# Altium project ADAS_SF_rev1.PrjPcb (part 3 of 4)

## Sheet ADAS_SF_Data_Deserializer_Radar.SchDoc
size 431 x 279 mm; Date: Not shown in title block; ApprovedBy: Not shown in title block; CheckedBy: Not shown in title block; Author: Not shown in title block; CompanyName: Not shown in title block; Engineer: Not shown in title block; Organization: Not shown in title block; Address1: Not shown in title block; Address2: Not shown in title block; Address3: Not shown in title block; Address4: Not shown in title block; DocumentNumber: 1; Revision: Use project parameter SCH_Rev; SheetNumber: 8; SheetTotal: 15; PageSetup: Record=PageOptions¦CenterHorizontal=True¦CenterVertical=True¦PrintScale=0.66¦XCorrection=1.00¦YCorrection=1.00¦PrintKind=0¦BorderSize=5000000¦LeftOffset=0¦BottomOffset=0¦Orientation=2¦PaperLength=1000¦PaperWidth=1000¦Scale=100¦PaperSource=15¦PrintQuality=600¦MediaType=1¦DitherType=10¦PrintScaleMode=1¦PaperKind=Letter
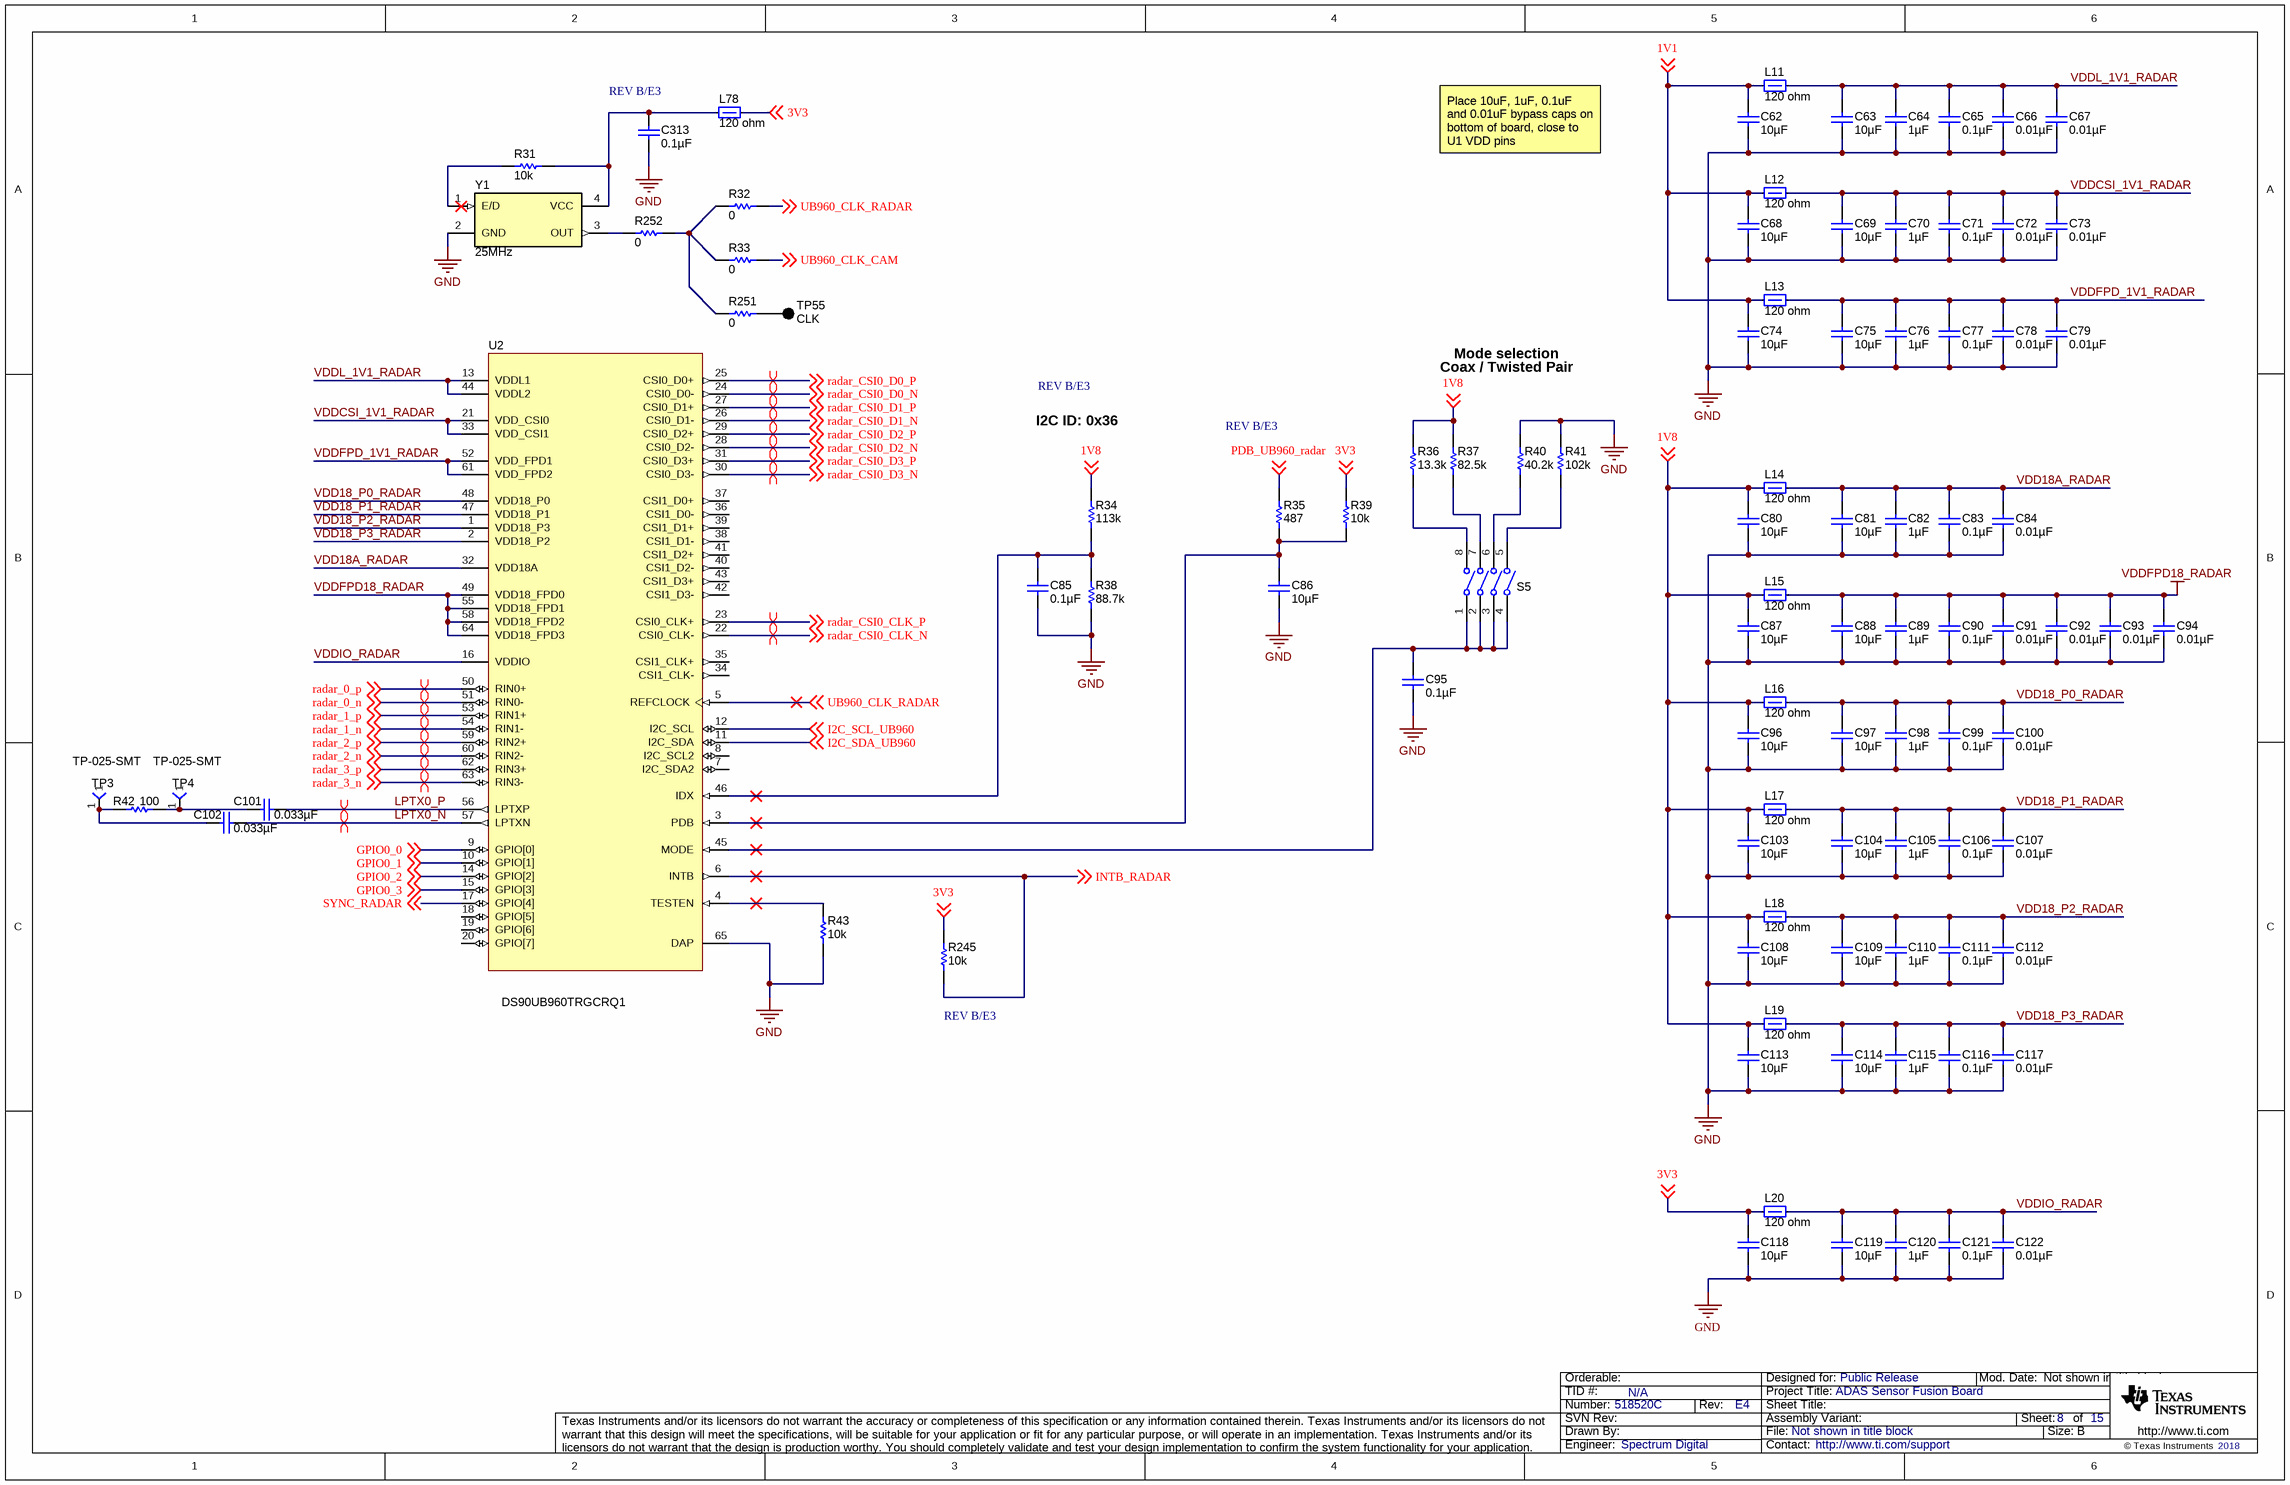
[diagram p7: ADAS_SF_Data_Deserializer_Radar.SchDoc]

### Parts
C62  ValueDisplayed: 10µF  [0805_HV]  (hidden comment: CL21A106KAFN3NE)
C63  ValueDisplayed: 10µF  [0805_HV]  (hidden comment: CL21A106KAFN3NE)
C64  ValueDisplayed: 1µF  [0402]  (hidden comment: C1005JB1V105K050BC)
C65  ValueDisplayed: 0.1µF  [0402]  (hidden comment: GCM155R71H104KE02D)
C66  ValueDisplayed: 0.01µF  [0402]  (hidden comment: GCM155R71H103KA55D)
C67  ValueDisplayed: 0.01µF  [0402]  (hidden comment: GCM155R71H103KA55D)
C68  ValueDisplayed: 10µF  [0805_HV]  (hidden comment: CL21A106KAFN3NE)
C69  ValueDisplayed: 10µF  [0805_HV]  (hidden comment: CL21A106KAFN3NE)
C70  ValueDisplayed: 1µF  [0402]  (hidden comment: C1005JB1V105K050BC)
C71  ValueDisplayed: 0.1µF  [0402]  (hidden comment: GCM155R71H104KE02D)
C72  ValueDisplayed: 0.01µF  [0402]  (hidden comment: GCM155R71H103KA55D)
C73  ValueDisplayed: 0.01µF  [0402]  (hidden comment: GCM155R71H103KA55D)
C74  ValueDisplayed: 10µF  [0805_HV]  (hidden comment: CL21A106KAFN3NE)
C75  ValueDisplayed: 10µF  [0805_HV]  (hidden comment: CL21A106KAFN3NE)
C76  ValueDisplayed: 1µF  [0402]  (hidden comment: C1005JB1V105K050BC)
C77  ValueDisplayed: 0.1µF  [0402]  (hidden comment: GCM155R71H104KE02D)
C78  ValueDisplayed: 0.01µF  [0402]  (hidden comment: GCM155R71H103KA55D)
C79  ValueDisplayed: 0.01µF  [0402]  (hidden comment: GCM155R71H103KA55D)
C80  ValueDisplayed: 10µF  [0805_HV]  (hidden comment: CL21A106KAFN3NE)
C81  ValueDisplayed: 10µF  [0805_HV]  (hidden comment: CL21A106KAFN3NE)
C82  ValueDisplayed: 1µF  [0402]  (hidden comment: C1005JB1V105K050BC)
C83  ValueDisplayed: 0.1µF  [0402]  (hidden comment: GCM155R71H104KE02D)
C84  ValueDisplayed: 0.01µF  [0402]  (hidden comment: GCM155R71H103KA55D)
C85  ValueDisplayed: 0.1µF  [0402]  (hidden comment: GCM155R71H104KE02D)
C86  ValueDisplayed: 10µF  [0805_HV]  (hidden comment: CL21A106KAFN3NE)
C87  ValueDisplayed: 10µF  [0805_HV]  (hidden comment: CL21A106KAFN3NE)
C88  ValueDisplayed: 10µF  [0805_HV]  (hidden comment: CL21A106KAFN3NE)
C89  ValueDisplayed: 1µF  [0402]  (hidden comment: C1005JB1V105K050BC)
C90  ValueDisplayed: 0.1µF  [0402]  (hidden comment: GCM155R71H104KE02D)
C91  ValueDisplayed: 0.01µF  [0402]  (hidden comment: GCM155R71H103KA55D)
C92  ValueDisplayed: 0.01µF  [0402]  (hidden comment: GCM155R71H103KA55D)
C93  ValueDisplayed: 0.01µF  [0402]  (hidden comment: GCM155R71H103KA55D)
C94  ValueDisplayed: 0.01µF  [0402]  (hidden comment: GCM155R71H103KA55D)
C95  ValueDisplayed: 0.1µF  [0402]  (hidden comment: GCM155R71H104KE02D)
C96  ValueDisplayed: 10µF  [0805_HV]  (hidden comment: CL21A106KAFN3NE)
C97  ValueDisplayed: 10µF  [0805_HV]  (hidden comment: CL21A106KAFN3NE)
C98  ValueDisplayed: 1µF  [0402]  (hidden comment: C1005JB1V105K050BC)
C99  ValueDisplayed: 0.1µF  [0402]  (hidden comment: GCM155R71H104KE02D)
C100  ValueDisplayed: 0.01µF  [0402]  (hidden comment: GCM155R71H103KA55D)
C101  ValueDisplayed: 0.033µF  [0402]  (hidden comment: CGA2B3X7R1H333K050BB)
C102  ValueDisplayed: 0.033µF  [0402]  (hidden comment: CGA2B3X7R1H333K050BB)
C103  ValueDisplayed: 10µF  [0805_HV]  (hidden comment: CL21A106KAFN3NE)
C104  ValueDisplayed: 10µF  [0805_HV]  (hidden comment: CL21A106KAFN3NE)
C105  ValueDisplayed: 1µF  [0402]  (hidden comment: C1005JB1V105K050BC)
C106  ValueDisplayed: 0.1µF  [0402]  (hidden comment: GCM155R71H104KE02D)
C107  ValueDisplayed: 0.01µF  [0402]  (hidden comment: GCM155R71H103KA55D)
C108  ValueDisplayed: 10µF  [0805_HV]  (hidden comment: CL21A106KAFN3NE)
C109  ValueDisplayed: 10µF  [0805_HV]  (hidden comment: CL21A106KAFN3NE)
C110  ValueDisplayed: 1µF  [0402]  (hidden comment: C1005JB1V105K050BC)
C111  ValueDisplayed: 0.1µF  [0402]  (hidden comment: GCM155R71H104KE02D)
C112  ValueDisplayed: 0.01µF  [0402]  (hidden comment: GCM155R71H103KA55D)
C113  ValueDisplayed: 10µF  [0805_HV]  (hidden comment: CL21A106KAFN3NE)
C114  ValueDisplayed: 10µF  [0805_HV]  (hidden comment: CL21A106KAFN3NE)
C115  ValueDisplayed: 1µF  [0402]  (hidden comment: C1005JB1V105K050BC)
C116  ValueDisplayed: 0.1µF  [0402]  (hidden comment: GCM155R71H104KE02D)
C117  ValueDisplayed: 0.01µF  [0402]  (hidden comment: GCM155R71H103KA55D)
C118  ValueDisplayed: 10µF  [0805_HV]  (hidden comment: CL21A106KAFN3NE)
C119  ValueDisplayed: 10µF  [0805_HV]  (hidden comment: CL21A106KAFN3NE)
C120  ValueDisplayed: 1µF  [0402]  (hidden comment: C1005JB1V105K050BC)
C121  ValueDisplayed: 0.1µF  [0402]  (hidden comment: GCM155R71H104KE02D)
C122  ValueDisplayed: 0.01µF  [0402]  (hidden comment: GCM155R71H103KA55D)
C313  ValueDisplayed: 0.1µF  [0402]  (hidden comment: GCM155R71H104KE02D)
L11  value 120 ohm  [0603]  (hidden comment: BLM18SG121TN1D)
L12  value 120 ohm  [0603]  (hidden comment: BLM18SG121TN1D)
L13  value 120 ohm  [0603]  (hidden comment: BLM18SG121TN1D)
L14  value 120 ohm  [0603]  (hidden comment: BLM18SG121TN1D)
L15  value 120 ohm  [0603]  (hidden comment: BLM18SG121TN1D)
L16  value 120 ohm  [0603]  (hidden comment: BLM18SG121TN1D)
L17  value 120 ohm  [0603]  (hidden comment: BLM18SG121TN1D)
L18  value 120 ohm  [0603]  (hidden comment: BLM18SG121TN1D)
L19  value 120 ohm  [0603]  (hidden comment: BLM18SG121TN1D)
L20  value 120 ohm  [0603]  (hidden comment: BLM18SG121TN1D)
L78  value 120 ohm  [0603]  (hidden comment: BLM18SG121TN1D)
R31  ValueDisplayed: 10k  [0402]  (hidden comment: CRCW040210K0JNED)
R32  ValueDisplayed: 0  [0603]  (hidden comment: CRCW06030000Z0EA)
R33  ValueDisplayed: 0  [0603]  (hidden comment: CRCW06030000Z0EA)
R34  ValueDisplayed: 113k  [0402]  (hidden comment: CRCW0402113KFKED)
R35  ValueDisplayed: 487  [0402]  (hidden comment: CRCW0402487RFKED)
R36  ValueDisplayed: 13.3k  [0402]  (hidden comment: CRCW040213K3FKED)
R37  ValueDisplayed: 82.5k  [0402]  (hidden comment: CRCW040282K5FKED)
R38  ValueDisplayed: 88.7k  [0402]  (hidden comment: CRCW040288K7FKED)
R39  ValueDisplayed: 10k  [0402]  (hidden comment: CRCW040210K0JNED)
R40  ValueDisplayed: 40.2k  [0402]  (hidden comment: CRCW040240K2FKED)
R41  ValueDisplayed: 102k  [0402]  (hidden comment: CRCW0402102KFKED)
R42  ValueDisplayed: 100  [0402]  (hidden comment: CRCW0402100RFKED)
R43  ValueDisplayed: 10k  [0402]  (hidden comment: CRCW040210K0JNED)
R245  ValueDisplayed: 10k  [0402]  (hidden comment: CRCW040210K0JNED)
R251  ValueDisplayed: 0  [0603]  (hidden comment: CRCW06030000Z0EA)
R252  ValueDisplayed: 0  [0603]  (hidden comment: CRCW06030000Z0EA)
S5  218-4LPST  [SW_218-4LPST]  (value not drawn)
TP3  TP-025-SMT  [TP_25MIL-SMT]
TP4  TP-025-SMT  [TP_25MIL-SMT]
TP55  CLK  [Keystone5011]
U2  DS90UB960TRGCRQ1  [RGC0064G]
Y1  Frequency: 25MHz  [TXC_7C]  (hidden comment: 7C-25.000MCB-T)

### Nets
1V1: C62.1 C68.1 C74.1 L11.1 L12.1 L13.1 ; off-sheet 1V1
1V8: C80.1 C87.1 C96.1 C103.1 C108.1 C113.1 L14.1 L15.1 L16.1 L17.1 L18.1 L19.1 R34.2 R36.2 R37.2 ; off-sheet 1V8
3V3: C118.1 L20.1 L78.2 R39.2 R245.2 ; off-sheet 3V3
GND: C62.2 C63.2 C64.2 C65.2 C66.2 C67.2 C68.2 C69.2 C70.2 C71.2 C72.2 C73.2 C74.2 C75.2 C76.2 C77.2 C78.2 C79.2 C80.2 C81.2 C82.2 C83.2 C84.2 C85.2 C86.2 C87.2 C88.2 C89.2 C90.2 C91.2 C92.2 C93.2 C94.2 C95.2 C96.2 C97.2 C98.2 C99.2 C100.2 C103.2 C104.2 C105.2 C106.2 C107.2 C108.2 C109.2 C110.2 C111.2 C112.2 C113.2 C114.2 C115.2 C116.2 C117.2 C118.2 C119.2 C120.2 C121.2 C122.2 C313.2 R38.1 R40.2 R41.2 R43.1 U2.65(DAP) Y1.2(GND)
VDDFPD18_RADAR: C88.1 C89.1 C90.1 C91.1 C92.1 C93.1 C94.1 L15.2 U2.49(VDD18_FPD0) U2.55(VDD18_FPD1) U2.58(VDD18_FPD2) U2.64(VDD18_FPD3)
GPIO0_0: U2.9(GPIO[0]) ; off-sheet GPIO0_0
GPIO0_1: U2.10(GPIO[1]) ; off-sheet GPIO0_1
GPIO0_2: U2.14(GPIO[2]) ; off-sheet GPIO0_2
GPIO0_3: U2.15(GPIO[3]) ; off-sheet GPIO0_3
I2C_SCL_UB960: U2.12(I2C_SCL) ; off-sheet I2C_SCL_UB960
I2C_SDA_UB960: U2.11(I2C_SDA) ; off-sheet I2C_SDA_UB960
INTB_RADAR: R245.1 U2.6(INTB) ; off-sheet INTB_RADAR
LPTX0_N: C102.1 U2.57(LPTXN)
LPTX0_P: C101.1 U2.56(LPTXP)
PDB_UB960_radar: R35.2 ; off-sheet PDB_UB960_radar
radar_0_n: U2.51(RIN0-) ; off-sheet radar_0_n
radar_0_p: U2.50(RIN0+) ; off-sheet radar_0_p
radar_1_n: U2.54(RIN1-) ; off-sheet radar_1_n
radar_1_p: U2.53(RIN1+) ; off-sheet radar_1_p
radar_2_n: U2.60(RIN2-) ; off-sheet radar_2_n
radar_2_p: U2.59(RIN2+) ; off-sheet radar_2_p
radar_3_n: U2.63(RIN3-) ; off-sheet radar_3_n
radar_3_p: U2.62(RIN3+) ; off-sheet radar_3_p
radar_CSI0_CLK_N: U2.22(CSI0_CLK-) ; off-sheet radar_CSI0_CLK_N
radar_CSI0_CLK_P: U2.23(CSI0_CLK+) ; off-sheet radar_CSI0_CLK_P
radar_CSI0_D0_N: U2.24(CSI0_D0-) ; off-sheet radar_CSI0_D0_N
radar_CSI0_D0_P: U2.25(CSI0_D0+) ; off-sheet radar_CSI0_D0_P
radar_CSI0_D1_N: U2.26(CSI0_D1-) ; off-sheet radar_CSI0_D1_N
radar_CSI0_D1_P: U2.27(CSI0_D1+) ; off-sheet radar_CSI0_D1_P
radar_CSI0_D2_N: U2.28(CSI0_D2-) ; off-sheet radar_CSI0_D2_N
radar_CSI0_D2_P: U2.29(CSI0_D2+) ; off-sheet radar_CSI0_D2_P
radar_CSI0_D3_N: U2.30(CSI0_D3-) ; off-sheet radar_CSI0_D3_N
radar_CSI0_D3_P: U2.31(CSI0_D3+) ; off-sheet radar_CSI0_D3_P
SYNC_RADAR: U2.17(GPIO[4]) ; off-sheet SYNC_RADAR
UB960_CLK_CAM: R33.2 ; off-sheet UB960_CLK_CAM
UB960_CLK_RADAR: R32.2 U2.5(REFCLOCK) ; off-sheet UB960_CLK_RADAR
VDD18_P0_RADAR: C97.1 C98.1 C99.1 C100.1 L16.2 U2.48(VDD18_P0)
VDD18_P1_RADAR: C104.1 C105.1 C106.1 C107.1 L17.2 U2.47(VDD18_P1)
VDD18_P2_RADAR: C109.1 C110.1 C111.1 C112.1 L18.2 U2.1(VDD18_P3)
VDD18_P3_RADAR: C114.1 C115.1 C116.1 C117.1 L19.2 U2.2(VDD18_P2)
VDD18A_RADAR: C81.1 C82.1 C83.1 C84.1 L14.2 U2.32(VDD18A)
VDDCSI_1V1_RADAR: C69.1 C70.1 C71.1 C72.1 C73.1 L12.2 U2.21(VDD_CSI0) U2.33(VDD_CSI1)
VDDFPD_1V1_RADAR: C75.1 C76.1 C77.1 C78.1 C79.1 L13.2 U2.52(VDD_FPD1) U2.61(VDD_FPD2)
VDDIO_RADAR: C119.1 C120.1 C121.1 C122.1 L20.2 U2.16(VDDIO)
VDDL_1V1_RADAR: C63.1 C64.1 C65.1 C66.1 C67.1 L11.2 U2.13(VDDL1) U2.44(VDDL2)
NetC85_1: C85.1 R34.1 R38.2 U2.46(IDX)
NetC86_1: C86.1 R35.1 R39.1 U2.3(PDB)
NetC95_1: C95.1 S5.1(A1) S5.2(A2) S5.3(A3) S5.4(A4) U2.45(MODE)
NetC101_2: C101.2 R42.1 TP4.1
NetC102_2: C102.2 R42.2 TP3.1
NetC313_1: C313.1 L78.1 R31.2 Y1.4(VCC)
NetR31_1: R31.1 Y1.1(E/D)
NetR32_1: R32.1 R33.1 R251.1 R252.2
NetR36_1: R36.1 S5.8(B1)
NetR37_1: R37.1 S5.7(B2)
NetR40_1: R40.1 S5.6(B3)
NetR41_1: R41.1 S5.5(B4)
NetR43_2: R43.2 U2.4(TESTEN)
NetR251_2: R251.2 TP55.1
NetR252_1: R252.1 Y1.3(OUT)

Not connected (* = marked no-connect by the designer): U2 7(I2C_SDA2) 8(I2C_SCL2) 18(GPIO[5]) 19(GPIO[6]) 20(GPIO[7]) 34(CSI1_CLK-) 35(CSI1_CLK+) 36(CSI1_D0-) 37(CSI1_D0+) 38(CSI1_D1-) 39(CSI1_D1+) 40(CSI1_D2-) 41(CSI1_D2+) 42(CSI1_D3-) 43(CSI1_D3+)

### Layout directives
differential pair: LPTX0_N, LPTX0_P, radar_0_n, radar_0_p, radar_1_n, radar_1_p, radar_2_n, radar_2_p, radar_3_n, radar_3_p, radar_CSI0_CLK_N, radar_CSI0_CLK_P, radar_CSI0_D0_N, radar_CSI0_D0_P, radar_CSI0_D1_N, radar_CSI0_D1_P, radar_CSI0_D2_N, radar_CSI0_D2_P, radar_CSI0_D3_N, radar_CSI0_D3_P

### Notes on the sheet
- (near C313) REV B/E3
- Place 10uF, 1uF, 0.1uF and 0.01uF bypass caps on bottom of board, close to U1 VDD pins
- Coax / Twisted Pair
- Mode selection
- REV B/E3
- I2C ID: 0x36
- (near R245) REV B/E3

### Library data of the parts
C62 C63 C68 C69 C74 C75 C80 C81 C87 C88 C96 C97 C103 C104 C108 C109 C113 C114 C118 C119 = CL21A106KAFN3NE: CAP, CERM, 10 µF, 25 V, +/- 10%, X5R, 0805; Manufacturer: Samsung; Polarized: N; CompType: Capacitor; Value: 10uF; U/M: EA; Cap_F: 0.00001; Tolerance_%: 10; Value1: Unknown; VDC_V: 25; Value2: 25V; TaMin_C: -55; TaMax_C: 85; Cap_Case: 0805
C64 C70 C76 C82 C89 C98 C105 C110 C115 C120 = C1005JB1V105K050BC: CAP, CERM, 1 µF, 35 V, +/- 10%, JB, 0402; Manufacturer: TDK; Polarized: N; CompType: Capacitor; Value: 1uF; U/M: EA; Cap_F: 0.000001; Tolerance_%: 10; Value1: Unknown; VDC_V: 35; Value2: 35V; TaMin_C: -25; TaMax_C: 85
C65 C71 C77 C83 C85 C90 C95 C99 C106 C111 C116 C121 C313 = GCM155R71H104KE02D: CAP, CERM, 0.1 µF, 50 V, +/- 10%, X7R, AEC-Q200 Grade 1, 0402; Manufacturer: MuRata; Polarized: N; CompType: Capacitor; Value: 0.1uF; U/M: EA; Cap_F: 0.0000001; Tolerance_%: 10; Value1: Unknown; VDC_V: 50; Value2: 50V; TaMin_C: -55; TaMax_C: 125; SizeArea_mm2: 0.5; SizeAreaWB_mm2: 3; SizeX_mm: 1; SizeZ_mm: 0.6; AEC Category: Q200; AEC Qualified: Y
C66 C67 C72 C73 C78 C79 C84 C91-C94 C100 C107 C112 C117 C122 = GCM155R71H103KA55D: CAP, CERM, 0.01uF, 50V, +/-10%, C0G/NP0, 0402; Manufacturer: MuRata; Polarized: N; CompType: Capacitor; U/M: EA; Cap_F: 0.00000001; Tolerance_%: 10; Value1: Unknown; VDC_V: 50; TaMin_C: -55; TaMax_C: 125
C86 = CL21A106KAFN3NE: CAP, CERM, 10 µF, 25 V, +/- 10%, X5R, 0805; Manufacturer: Samsung Electro-Mechanics; Polarized: N; CompType: Capacitor; Value: 10uF; U/M: EA; Cap_F: 0.00001; Tolerance_%: 10; Value1: Unknown; VDC_V: 25; Value2: 25V; TaMin_C: -55; TaMax_C: 85; Cap_Case: 0805; SizeArea_mm2: 2.5; SizeAreaWB_mm2: 6.75; SizeX_mm: 2; SizeY_mm: 1.25; SizeZ_mm: 1.45; AEC Category: Q200
C101 C102 = CGA2B3X7R1H333K050BB: CAP, CERM, 0.033 µF, 50 V, +/- 10%, X7R, AEC-Q200 Grade 1, 0402; Manufacturer: TDK; Polarized: N; CompType: Capacitor; Value: 0.033uF; U/M: EA; Cap_F: 0.000000033; Tolerance_%: 10; Value1: Unknown; VDC_V: 50; Value2: 50V; TaMin_C: -55; TaMax_C: 125; AEC Category: Q200; AEC Qualified: Y; AEC Grade: 1
L11-L13 L15-L19 L78 = BLM18SG331TN1D: 1.5A Ferrite Bead, 330 ohm @ 100MHz, SMD; Manufacturer: MuRata; Imax_A: 3; DCR_ohm: 25milliiohm; Value1: 25 milliohm; Value2: 3A; ZTyp@100MHz_Ohm: 120; U/M: EA
L14 L20 = BLM18SG121TN1D: Ferrite Bead, 120 ohm @ 100 MHz, 3 A, 0603; Manufacturer: MuRata; Imax_A: 3; DCR_ohm: 0.025; Value1: 0.025 ohm; Value2: 3A; ZTyp@100MHz_Ohm: 120
R31 R43 = CRCW040210K0JNED: RES, 10 k, 5%, 0.063 W, 0402; Manufacturer: Vishay-Dale; CompType: Resistor; Value: 10k; Res_ohm: 10000; Value_Code: 10k0; Tolerance_%: 5; Power_W: 0.063; Value2: 0.063W; VDC_V: 50; TempCo: 200 ppm/C; EIA_Code: E24; U/M: EA; AEC Category: Q200
R32 R33 R251 R252 = CRCW06030000Z0EA: RES, 0, 5%, 0.1 W, 0603; Manufacturer: Vishay-Dale; CompType: Resistor; Value: 0; Value_Code: 0000; Tolerance_%: 5; Power_W: 0.1; Value2: 0.1W; VDC_V: 75; TempCo: 200 ppm/C; SizeArea_mm2: 1.28; SizeX_mm: 1.6; SizeY_mm: 0.8; SizeZ_mm: 1; EIA_Code: E24; U/M: EA; AEC Category: Q200
R34 = CRCW0402113KFKED: RES, 113 k, 1%, 0.063 W, 0402; Manufacturer: Vishay-Dale; CompType: Resistor; Value: 113k; Res_ohm: 113000; Tolerance_%: 1; Power_W: 0.063; Value2: 0.063W; VDC_V: 50; TempCo: 100 ppm/C; EIA_Code: E96; U/M: EA; AEC Category: Q200; SizeArea_mm2: 0.5; SizeZ_mm: 0.6
R35 = CRCW0402487RFKED: RES, 487, 1%, 0.063 W, 0402; Manufacturer: Vishay-Dale; CompType: Resistor; Value: 487; Value_Code: 487R; Tolerance_%: 1; Power_W: 0.063; Value2: 0.063W; VDC_V: 50; TempCo: 100 ppm/C; EIA_Code: E96; U/M: EA; AEC Category: Q200; SizeArea_mm2: 0.5; SizeZ_mm: 0.6
R36 = CRCW040213K3FKED: RES, 13.3 k, 1%, 0.063 W, 0402; Manufacturer: Vishay-Dale; CompType: Resistor; Value: 13.3k; Res_ohm: 13300; Value_Code: 13k3; Tolerance_%: 1; Power_W: 0.063; Value2: 0.063W; VDC_V: 50; TempCo: 100 ppm/C; EIA_Code: E96; U/M: EA; AEC Category: Q200
R37 = CRCW040282K5FKED: RES, 82.5 k, 1%, 0.063 W, 0402; Manufacturer: Vishay-Dale; CompType: Resistor; Value: 82.5k; Res_ohm: 82500; Value_Code: 82k5; Tolerance_%: 1; Power_W: 0.063; Value2: 0.063W; VDC_V: 50; TempCo: 100 ppm/C; EIA_Code: E96; U/M: EA; AEC Category: Q200
R38 = CRCW040288K7FKED: RES, 88.7 k, 1%, 0.063 W, 0402; Manufacturer: Vishay-Dale; CompType: Resistor; Value: 88.7k; Res_ohm: 88700; Value_Code: 88k7; Tolerance_%: 1; Power_W: 0.063; Value2: 0.063W; VDC_V: 50; TempCo: 100 ppm/C; EIA_Code: E96; U/M: EA; AEC Category: Q200; SizeArea_mm2: 0.5; SizeZ_mm: 0.6
R39 R245 = CRCW040210K0JNED: RES, 10 k, 5%, 0.063 W, 0402; Manufacturer: Vishay-Dale; CompType: Resistor; Value: 10k; Res_ohm: 10000; Value_Code: 10k0; Tolerance_%: 5; Power_W: 0.063; Value2: 0.063W; VDC_V: 50; TempCo: 200 ppm/C; EIA_Code: E24; U/M: EA; AEC Category: Q200; SizeArea_mm2: 0.5; SizeX_mm: 1; SizeZ_mm: 0.6
R40 = CRCW040240K2FKED: RES, 40.2 k, 1%, 0.063 W, 0402; Manufacturer: Vishay-Dale; CompType: Resistor; Value: 40.2k; Res_ohm: 40200; Value_Code: 40k2; Tolerance_%: 1; Power_W: 0.063; Value2: 0.063W; VDC_V: 50; TempCo: 100 ppm/C; EIA_Code: E96; U/M: EA; AEC Category: Q200
R41 = CRCW0402102KFKED: RES, 102 k, 1%, 0.063 W, 0402; Manufacturer: Vishay-Dale; CompType: Resistor; Value: 102k; Res_ohm: 102000; Tolerance_%: 1; Power_W: 0.063; Value2: 0.063W; VDC_V: 50; TempCo: 100 ppm/C; EIA_Code: E96; U/M: EA; AEC Category: Q200
R42 = CRCW0402100RFKED: RES, 100, 1%, 0.063 W, 0402; Manufacturer: Vishay-Dale; CompType: Resistor; Value: 100; Value_Code: 100R; Tolerance_%: 1; Power_W: 0.063; Value2: 0.063W; VDC_V: 50; TempCo: 100 ppm/C; EIA_Code: E96; U/M: EA; AEC Category: Q200
S5 = 218-4LPST: Switch, Slide, SPST 4 poles, SMT; Manufacturer: CTS Electrocomponents; SymbolCreator: a0412235; VDC_V: 24; SwitchFunction: Off-On; PositionCount: 4; CurrentRating_mA: 25
TP3 TP4 = TP-025-SMT: Test Point, O.025"; Manufacturer: STD; Value: STD
TP55 = 5011: Test Point, Multipurpose, Black, TH; Manufacturer: Keystone; CompType: Test Point Loop; U/M: EA
U2 = DS90UB960TRGCRQ1: FPD-Link III Camera Hub Deserializer, RGC0064G; Alternate PartNumber: DS90UB960TRGCTQ1; Manufacturer: Texas Instruments; SymbolCreator: Altium; CompType: IC; U/M: EA
Y1 = 7C-25.000MCB-T: XO, 25.000MHz, 2.5V, SMD; Manufacturer: TXC Corporation; SymbolCreator: a0411947; CompType: Oscillator; U/M: EA; TaMin_C: -40; TaMax_C: 85; Frequency Stability: ±50ppm

## Sheet ADAS_SF_Data_Radar_Mux.SchDoc
size 431 x 279 mm; Date: Not shown in title block; ApprovedBy: Not shown in title block; CheckedBy: Not shown in title block; Author: Not shown in title block; CompanyName: Not shown in title block; Engineer: Not shown in title block; Organization: Not shown in title block; Address1: Not shown in title block; Address2: Not shown in title block; Address3: Not shown in title block; Address4: Not shown in title block; DocumentNumber: 1; Revision: Use project parameter SCH_Rev; SheetNumber: 9; SheetTotal: 15; PageSetup: Record=PageOptions¦CenterHorizontal=True¦CenterVertical=True¦PrintScale=1.00¦XCorrection=1.00¦YCorrection=1.00¦PrintKind=0¦BorderSize=5000000¦LeftOffset=0¦BottomOffset=0¦Orientation=2¦PaperLength=1000¦PaperWidth=1000¦Scale=100¦PaperSource=15¦PrintQuality=600¦MediaType=1¦DitherType=10¦PaperKind=Letter¦PrintScaleMode=1
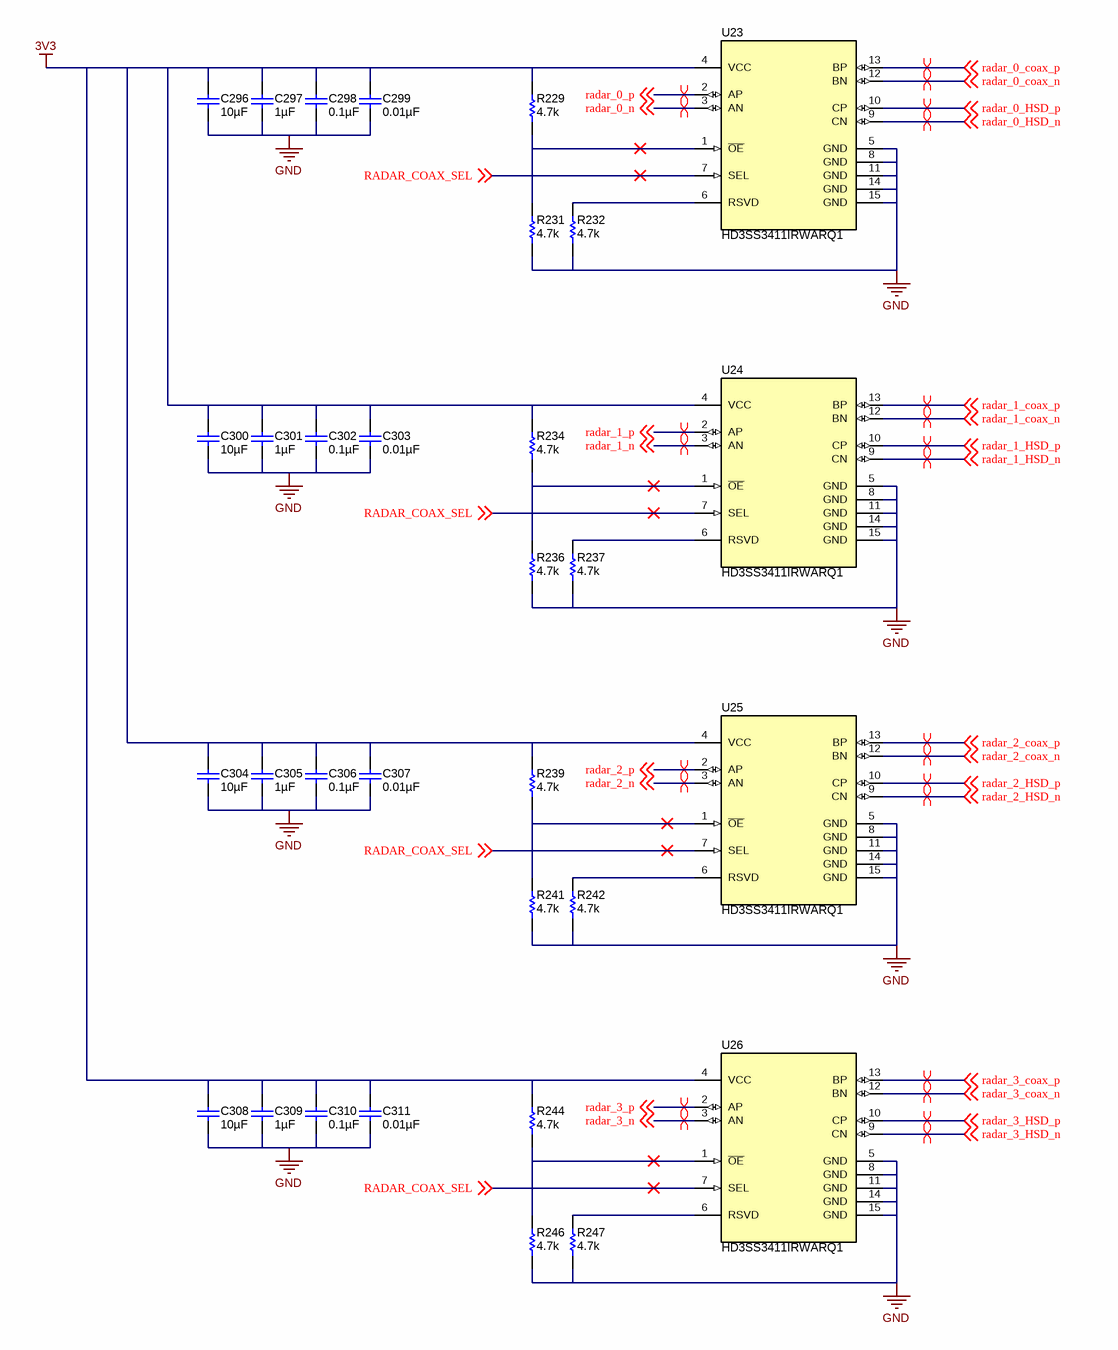
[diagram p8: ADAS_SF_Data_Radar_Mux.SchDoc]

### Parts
C296  ValueDisplayed: 10µF  [0805_HV]  (hidden comment: CL21A106KAFN3NE)
C297  ValueDisplayed: 1µF  [0402]  (hidden comment: C1005JB1V105K050BC)
C298  ValueDisplayed: 0.1µF  [0402]  (hidden comment: GCM155R71H104KE02D)
C299  ValueDisplayed: 0.01µF  [0402]  (hidden comment: GCM155R71H103KA55D)
C300  ValueDisplayed: 10µF  [0805_HV]  (hidden comment: CL21A106KAFN3NE)
C301  ValueDisplayed: 1µF  [0402]  (hidden comment: C1005JB1V105K050BC)
C302  ValueDisplayed: 0.1µF  [0402]  (hidden comment: GCM155R71H104KE02D)
C303  ValueDisplayed: 0.01µF  [0402]  (hidden comment: GCM155R71H103KA55D)
C304  ValueDisplayed: 10µF  [0805_HV]  (hidden comment: CL21A106KAFN3NE)
C305  ValueDisplayed: 1µF  [0402]  (hidden comment: C1005JB1V105K050BC)
C306  ValueDisplayed: 0.1µF  [0402]  (hidden comment: GCM155R71H104KE02D)
C307  ValueDisplayed: 0.01µF  [0402]  (hidden comment: GCM155R71H103KA55D)
C308  ValueDisplayed: 10µF  [0805_HV]  (hidden comment: CL21A106KAFN3NE)
C309  ValueDisplayed: 1µF  [0402]  (hidden comment: C1005JB1V105K050BC)
C310  ValueDisplayed: 0.1µF  [0402]  (hidden comment: GCM155R71H104KE02D)
C311  ValueDisplayed: 0.01µF  [0402]  (hidden comment: GCM155R71H103KA55D)
R229  ValueDisplayed: 4.7k  [0402]  (hidden comment: CRCW04024K70JNED)
R231  ValueDisplayed: 4.7k  [0402]  (hidden comment: CRCW04024K70JNED)
R232  ValueDisplayed: 4.7k  [0402]  (hidden comment: CRCW04024K70JNED)
R234  ValueDisplayed: 4.7k  [0402]  (hidden comment: CRCW04024K70JNED)
R236  ValueDisplayed: 4.7k  [0402]  (hidden comment: CRCW04024K70JNED)
R237  ValueDisplayed: 4.7k  [0402]  (hidden comment: CRCW04024K70JNED)
R239  ValueDisplayed: 4.7k  [0402]  (hidden comment: CRCW04024K70JNED)
R241  ValueDisplayed: 4.7k  [0402]  (hidden comment: CRCW04024K70JNED)
R242  ValueDisplayed: 4.7k  [0402]  (hidden comment: CRCW04024K70JNED)
R244  ValueDisplayed: 4.7k  [0402]  (hidden comment: CRCW04024K70JNED)
R246  ValueDisplayed: 4.7k  [0402]  (hidden comment: CRCW04024K70JNED)
R247  ValueDisplayed: 4.7k  [0402]  (hidden comment: CRCW04024K70JNED)
U23  HD3SS3411IRWARQ1  [RWA0014A]
U24  HD3SS3411IRWARQ1  [RWA0014A]
U25  HD3SS3411IRWARQ1  [RWA0014A]
U26  HD3SS3411IRWARQ1  [RWA0014A]

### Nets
3V3: C296.1 C297.1 C298.1 C299.1 C300.1 C301.1 C302.1 C303.1 C304.1 C305.1 C306.1 C307.1 C308.1 C309.1 C310.1 C311.1 R229.2 R234.2 R239.2 R244.2 U23.4(VCC) U24.4(VCC) U25.4(VCC) U26.4(VCC)
GND: C296.2 C297.2 C298.2 C299.2 C300.2 C301.2 C302.2 C303.2 C304.2 C305.2 C306.2 C307.2 C308.2 C309.2 C310.2 C311.2 R231.1 R232.1 R236.1 R237.1 R241.1 R242.1 R246.1 R247.1 U23.5(GND) U23.8(GND) U23.11(GND) U23.14(GND) U23.15(GND) U24.5(GND) U24.8(GND) U24.11(GND) U24.14(GND) U24.15(GND) U25.5(GND) U25.8(GND) U25.11(GND) U25.14(GND) U25.15(GND) U26.5(GND) U26.8(GND) U26.11(GND) U26.14(GND) U26.15(GND)
radar_0_coax_n: U23.12(BN) ; off-sheet radar_0_coax_n
radar_0_coax_p: U23.13(BP) ; off-sheet radar_0_coax_p
radar_0_HSD_n: U23.9(CN) ; off-sheet radar_0_HSD_n
radar_0_HSD_p: U23.10(CP) ; off-sheet radar_0_HSD_p
radar_0_n: U23.3(AN) ; off-sheet radar_0_n
radar_0_p: U23.2(AP) ; off-sheet radar_0_p
radar_1_coax_n: U24.12(BN) ; off-sheet radar_1_coax_n
radar_1_coax_p: U24.13(BP) ; off-sheet radar_1_coax_p
radar_1_HSD_n: U24.9(CN) ; off-sheet radar_1_HSD_n
radar_1_HSD_p: U24.10(CP) ; off-sheet radar_1_HSD_p
radar_1_n: U24.3(AN) ; off-sheet radar_1_n
radar_1_p: U24.2(AP) ; off-sheet radar_1_p
radar_2_coax_n: U25.12(BN) ; off-sheet radar_2_coax_n
radar_2_coax_p: U25.13(BP) ; off-sheet radar_2_coax_p
radar_2_HSD_n: U25.9(CN) ; off-sheet radar_2_HSD_n
radar_2_HSD_p: U25.10(CP) ; off-sheet radar_2_HSD_p
radar_2_n: U25.3(AN) ; off-sheet radar_2_n
radar_2_p: U25.2(AP) ; off-sheet radar_2_p
radar_3_coax_n: U26.12(BN) ; off-sheet radar_3_coax_n
radar_3_coax_p: U26.13(BP) ; off-sheet radar_3_coax_p
radar_3_HSD_n: U26.9(CN) ; off-sheet radar_3_HSD_n
radar_3_HSD_p: U26.10(CP) ; off-sheet radar_3_HSD_p
radar_3_n: U26.3(AN) ; off-sheet radar_3_n
radar_3_p: U26.2(AP) ; off-sheet radar_3_p
RADAR_COAX_SEL: U23.7(SEL) U24.7(SEL) U25.7(SEL) U26.7(SEL) ; off-sheet RADAR_COAX_SEL
NetR229_1: R229.1 R231.2 U23.1(~{OE})
NetR232_2: R232.2 U23.6(RSVD)
NetR234_1: R234.1 R236.2 U24.1(~{OE})
NetR237_2: R237.2 U24.6(RSVD)
NetR239_1: R239.1 R241.2 U25.1(~{OE})
NetR242_2: R242.2 U25.6(RSVD)
NetR244_1: R244.1 R246.2 U26.1(~{OE})
NetR247_2: R247.2 U26.6(RSVD)

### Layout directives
differential pair: radar_0_coax_n, radar_0_coax_p, radar_0_HSD_n, radar_0_HSD_p, radar_0_n, radar_0_p, radar_1_coax_n, radar_1_coax_p, radar_1_HSD_n, radar_1_HSD_p, radar_1_n, radar_1_p, radar_2_coax_n, radar_2_coax_p, radar_2_HSD_n, radar_2_HSD_p, radar_2_n, radar_2_p, radar_3_coax_n, radar_3_coax_p, radar_3_HSD_n, radar_3_HSD_p, radar_3_n, radar_3_p

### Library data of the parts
C296 C300 C304 C308 = CL21A106KAFN3NE: as C62 on sheet ADAS_SF_Data_Deserializer_Radar
C297 C301 C305 C309 = C1005JB1V105K050BC: as C64 on sheet ADAS_SF_Data_Deserializer_Radar
C298 C302 C306 C310 = GCM155R71H104KE02D: as C65 on sheet ADAS_SF_Data_Deserializer_Radar
C299 C303 C307 C311 = GCM155R71H103KA55D: as C66 on sheet ADAS_SF_Data_Deserializer_Radar
R229 R231 R232 R234 R236 R237 R239 R241 R242 R244 R246 R247 = CRCW04024K70JNED: RES, 4.7 k, 5%, 0.063 W, 0402; Manufacturer: Vishay-Dale; CompType: Resistor; Value: 4.7k; Res_ohm: 4700; Value_Code: 4k70; Tolerance_%: 5; Power_W: 0.063; Value2: 0.063W; VDC_V: 50; TempCo: 200 ppm/C; SizeArea_mm2: 0.5; SizeX_mm: 1; SizeZ_mm: 0.6; EIA_Code: E24; U/M: EA; AEC Category: Q200
U23-U26 = HD3SS3411IRWARQ1: One Channel Differential 2:1 Mux/Demux, RWA0014A; Alternate PartNumber: HD3SS3411IRWAQ1; Manufacturer: Texas Instruments; SymbolCreator: Altium; SizeArea_mm2: 12.25; SizeAreaWB_mm2: 20.25; SizeX_mm: 3.5; SizeZ_mm: 0.8; CompType: IC; U/M: EA

## Sheet ADAS_SF_Data_Connection_Radar_01.SchDoc
size 431 x 279 mm; Date: Not shown in title block; ApprovedBy: Not shown in title block; CheckedBy: Not shown in title block; Author: Not shown in title block; CompanyName: Not shown in title block; Engineer: Not shown in title block; Organization: Not shown in title block; Address1: Not shown in title block; Address2: Not shown in title block; Address3: Not shown in title block; Address4: Not shown in title block; DocumentNumber: 1; Revision: Use project parameter SCH_Rev; SheetNumber: 10; SheetTotal: 15; PageSetup: Record=PageOptions¦CenterHorizontal=True¦CenterVertical=True¦PrintScale=1.00¦XCorrection=1.00¦YCorrection=1.00¦PrintKind=0¦BorderSize=5000000¦LeftOffset=0¦BottomOffset=0¦Orientation=2¦PaperLength=1000¦PaperWidth=1000¦Scale=100¦PaperSource=15¦PrintQuality=600¦MediaType=1¦DitherType=10¦PaperKind=Letter¦PrintScaleMode=1
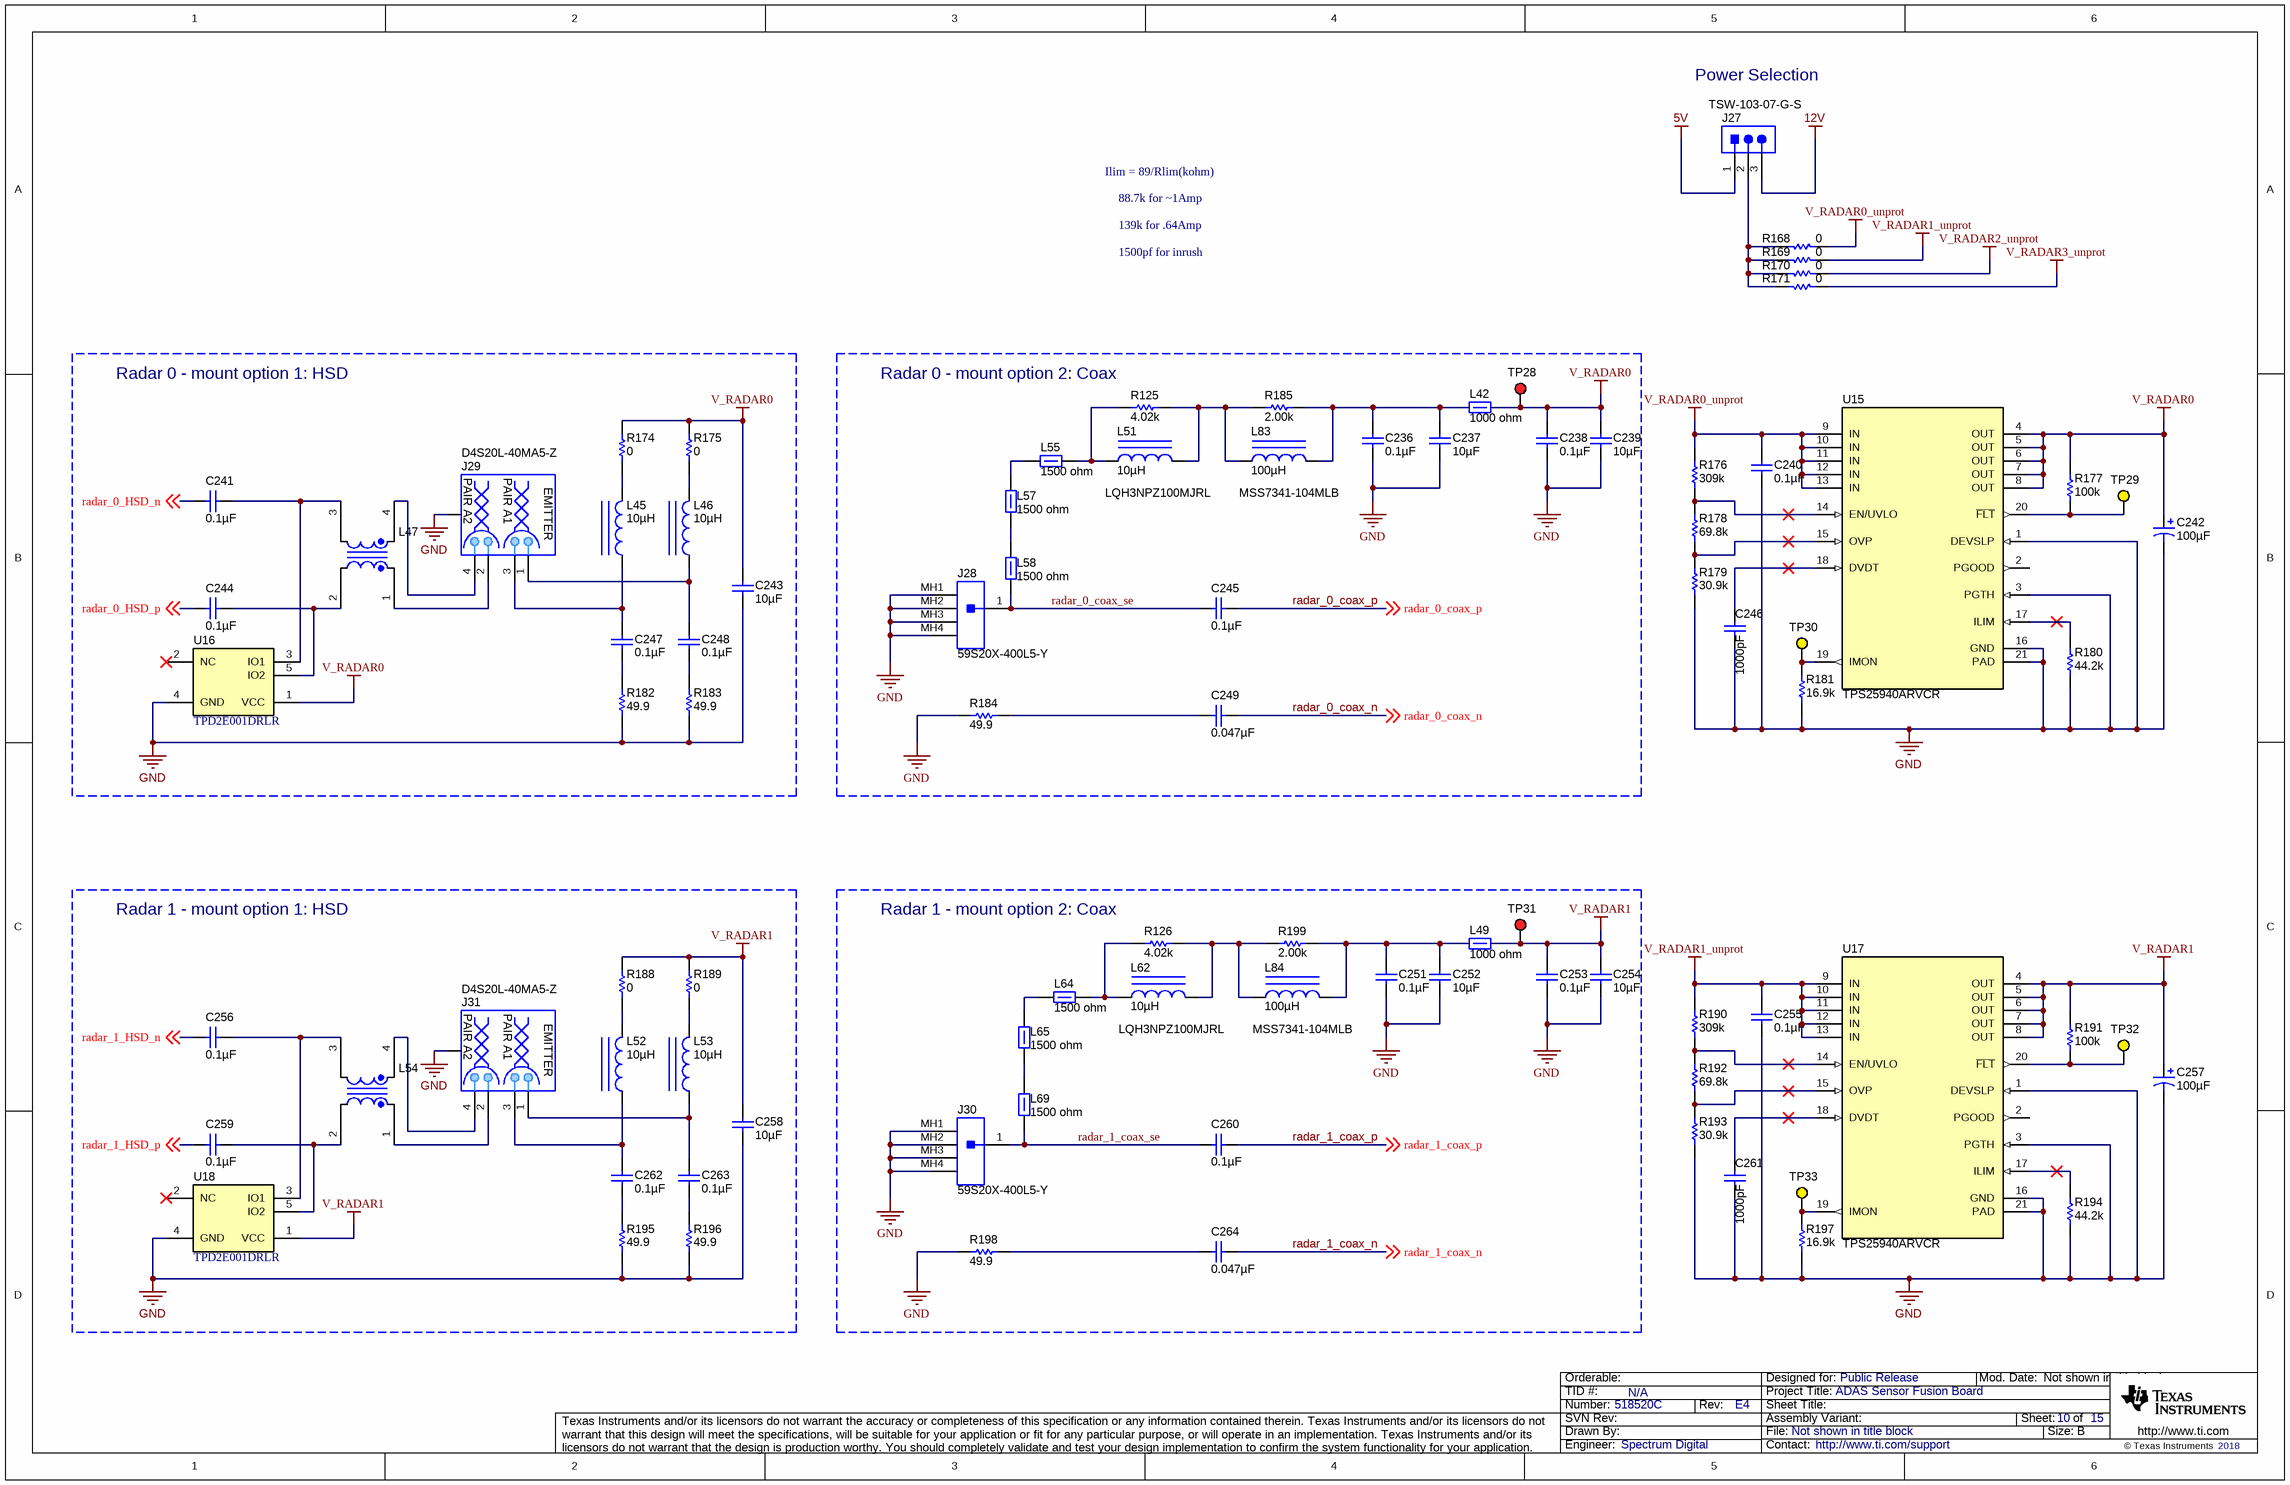
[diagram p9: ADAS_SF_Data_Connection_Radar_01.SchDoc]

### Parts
C236  ValueDisplayed: 0.1µF  [0402]  (hidden comment: GCM155R71H104KE02D)
C237  ValueDisplayed: 10µF  [0805_HV]  (hidden comment: TMK212BBJ106KG-T)
C238  ValueDisplayed: 0.1µF  [0402]  (hidden comment: GCM155R71H104KE02D)
C239  ValueDisplayed: 10µF  [0805_HV]  (hidden comment: TMK212BBJ106KG-T)
C240  ValueDisplayed: 0.1µF  [0603L]  (hidden comment: GRM188R72A104KA35D)
C241  ValueDisplayed: 0.1µF  [0402]  (hidden comment: GCM155R71H104KE02D)
C242  ValueDisplayed: 100µF  [SM_RADIAL_E]  (hidden comment: EEE-FC1C101P)
C243  ValueDisplayed: 10µF  [0805_HV]  (hidden comment: CL21A106KAFN3NE)
C244  ValueDisplayed: 0.1µF  [0402]  (hidden comment: GCM155R71H104KE02D)
C245  ValueDisplayed: 0.1µF  [0402]  (hidden comment: GCM155R71H104KE02D)
C246  ValueDisplayed: 1000pF  [0402]  (hidden comment: GCM155R71H102KA37D)
C247  ValueDisplayed: 0.1µF  [0603]  (hidden comment: GRM188R72A104KA35D)
C248  ValueDisplayed: 0.1µF  [0603]  (hidden comment: GRM188R72A104KA35D)
C249  ValueDisplayed: 0.047µF  [0402]  (hidden comment: CGA2B3X7R1H473K050BB)
C251  ValueDisplayed: 0.1µF  [0402]  (hidden comment: GCM155R71H104KE02D)
C252  ValueDisplayed: 10µF  [0805_HV]  (hidden comment: TMK212BBJ106KG-T)
C253  ValueDisplayed: 0.1µF  [0402]  (hidden comment: GCM155R71H104KE02D)
C254  ValueDisplayed: 10µF  [0805_HV]  (hidden comment: TMK212BBJ106KG-T)
C255  ValueDisplayed: 0.1µF  [0603L]  (hidden comment: GRM188R72A104KA35D)
C256  ValueDisplayed: 0.1µF  [0402]  (hidden comment: GCM155R71H104KE02D)
C257  ValueDisplayed: 100µF  [SM_RADIAL_E]  (hidden comment: EEE-FC1C101P)
C258  ValueDisplayed: 10µF  [0805_HV]  (hidden comment: CL21A106KAFN3NE)
C259  ValueDisplayed: 0.1µF  [0402]  (hidden comment: GCM155R71H104KE02D)
C260  ValueDisplayed: 0.1µF  [0402]  (hidden comment: GCM155R71H104KE02D)
C261  ValueDisplayed: 1000pF  [0402]  (hidden comment: GCM155R71H102KA37D)
C262  ValueDisplayed: 0.1µF  [0603]  (hidden comment: GRM188R72A104KA35D)
C263  ValueDisplayed: 0.1µF  [0603]  (hidden comment: GRM188R72A104KA35D)
C264  ValueDisplayed: 0.047µF  [0402]  (hidden comment: CGA2B3X7R1H473K050BB)
J27  TSW-103-07-G-S  [TSW-103-07-G-S]
J28  59S20X-400L5-Y  [Rosenberger_59S20X-400L5]
J29  D4S20L-40MA5-Z  [Rosenberger_D4S20L-40MA5]
J30  59S20X-400L5-Y  [Rosenberger_59S20X-400L5]
J31  D4S20L-40MA5-Z  [Rosenberger_D4S20L-40MA5]
L42  value 1000 ohm  [0603]  (hidden comment: MPZ1608S102ATA00)
L45  ValueDisplayed: 10µH  [EPL3012]  (hidden comment: EPL3012-103MLB)
L46  ValueDisplayed: 10µH  [EPL3012]  (hidden comment: EPL3012-103MLB)
L47  DLW21HN900SQ2L  [DLW21H]  (value not drawn)
L49  value 1000 ohm  [0603]  (hidden comment: MPZ1608S102ATA00)
L51  LQH3NPZ100MJRL  ValueDisplayed: 10µH  [LQH3NPZ_JR]
L52  ValueDisplayed: 10µH  [EPL3012]  (hidden comment: EPL3012-103MLB)
L53  ValueDisplayed: 10µH  [EPL3012]  (hidden comment: EPL3012-103MLB)
L54  DLW21HN900SQ2L  [DLW21H]  (value not drawn)
L55  ValueDisplayed: 1500 ohm  [0603]  (hidden comment: BLM18HE152SN1D)
L57  ValueDisplayed: 1500 ohm  [0603]  (hidden comment: BLM18HE152SN1D)
L58  ValueDisplayed: 1500 ohm  [0603]  (hidden comment: BLM18HE152SN1D)
L62  LQH3NPZ100MJRL  ValueDisplayed: 10µH  [LQH3NPZ_JR]
L64  ValueDisplayed: 1500 ohm  [0603]  (hidden comment: BLM18HE152SN1D)
L65  ValueDisplayed: 1500 ohm  [0603]  (hidden comment: BLM18HE152SN1D)
L69  ValueDisplayed: 1500 ohm  [0603]  (hidden comment: BLM18HE152SN1D)
L83  MSS7341-104MLB  ValueDisplayed: 100µH  [MSS7341]
L84  MSS7341-104MLB  ValueDisplayed: 100µH  [MSS7341]
R125  ValueDisplayed: 4.02k  [0603]  (hidden comment: CRCW06034K02FKEA)
R126  ValueDisplayed: 4.02k  [0603]  (hidden comment: CRCW06034K02FKEA)
R168  value 0  [0603]  (hidden comment: CRCW06030000Z0EA)
R169  value 0  [0603]  (hidden comment: CRCW06030000Z0EA)
R170  value 0  [0603]  (hidden comment: CRCW06030000Z0EA)
R171  value 0  [0603]  (hidden comment: CRCW06030000Z0EA)
R174  ValueDisplayed: 0  [0603]  (hidden comment: CRCW06030000Z0EA)
R175  ValueDisplayed: 0  [0603]  (hidden comment: CRCW06030000Z0EA)
R176  ValueDisplayed: 309k  [0402]  (hidden comment: CRCW0402309KFKED)
R177  ValueDisplayed: 100k  [0402]  (hidden comment: CRCW0402100KDHEDP)
R178  ValueDisplayed: 69.8k  [0402]  (hidden comment: CRCW040269K8FKED)
R179  ValueDisplayed: 30.9k  [0402]  (hidden comment: CRCW040230K9FKED)
R180  ValueDisplayed: 44.2k  [0402]  (hidden comment: CRCW040244K2FKED)
R181  ValueDisplayed: 16.9k  [0402]  (hidden comment: CRCW040216K9FKED)
R182  ValueDisplayed: 49.9  [0402]  (hidden comment: CRCW040249R9FKED)
R183  ValueDisplayed: 49.9  [0402]  (hidden comment: CRCW040249R9FKED)
R184  ValueDisplayed: 49.9  [0402]  (hidden comment: CRCW040249R9FKED)
R185  ValueDisplayed: 2.00k  [0603]  (hidden comment: CRCW06032K00FKEA)
R188  ValueDisplayed: 0  [0603]  (hidden comment: CRCW06030000Z0EA)
R189  ValueDisplayed: 0  [0603]  (hidden comment: CRCW06030000Z0EA)
R190  ValueDisplayed: 309k  [0402]  (hidden comment: CRCW0402309KFKED)
R191  ValueDisplayed: 100k  [0402]  (hidden comment: CRCW0402100KDHEDP)
R192  ValueDisplayed: 69.8k  [0402]  (hidden comment: CRCW040269K8FKED)
R193  ValueDisplayed: 30.9k  [0402]  (hidden comment: CRCW040230K9FKED)
R194  ValueDisplayed: 44.2k  [0402]  (hidden comment: CRCW040244K2FKED)
R195  ValueDisplayed: 49.9  [0402]  (hidden comment: CRCW040249R9FKED)
R196  ValueDisplayed: 49.9  [0402]  (hidden comment: CRCW040249R9FKED)
R197  ValueDisplayed: 16.9k  [0402]  (hidden comment: CRCW040216K9FKED)
R198  ValueDisplayed: 49.9  [0402]  (hidden comment: CRCW040249R9FKED)
R199  ValueDisplayed: 2.00k  [0603]  (hidden comment: CRCW06032K00FKEA)
TP28  5000  [Keystone5000]  (value not drawn)
TP29  5004  [Keystone5004]  (value not drawn)
TP30  5004  [Keystone5004]  (value not drawn)
TP31  5000  [Keystone5000]  (value not drawn)
TP32  5004  [Keystone5004]  (value not drawn)
TP33  5004  [Keystone5004]  (value not drawn)
U15  TPS25940ARVCR  [RVC0020A]
U16  TPD2E001DRLR  [DRL0005A]
U17  TPS25940ARVCR  [RVC0020A]
U18  TPD2E001DRLR  [DRL0005A]

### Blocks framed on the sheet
Radar 0 - mount option 1: HSD: C241 C243 C244 C247 C248 J29 L45-L47 R174 R175 R182 R183 U16
Radar 0 - mount option 2: Coax: C236-C239 C245 C249 J28 L42 L51 L55 L57 L58 L83 R125 R184 R185 TP28
Radar 1 - mount option 1: HSD: C256 C258 C259 C262 C263 J31 L52-L54 R188 R189 R195 R196 U18
Radar 1 - mount option 2: Coax: C251-C254 C260 C264 J30 L49 L62 L64 L65 L69 L84 R126 R198 R199 TP31

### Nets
5V: J27.1
12V: J27.3
GND: C236.2 C237.2 C238.2 C239.2 C240.1 C242.2(-) C243.2 C246.2 C251.2 C252.2 C253.2 C254.2 C255.1 C257.2(-) C258.2 C261.2 J28.MH1 J28.MH2 J28.MH3 J28.MH4 J29.MH J30.MH1 J30.MH2 J30.MH3 J30.MH4 J31.MH R179.1 R180.1 R181.1 R182.1 R183.1 R184.1 R193.1 R194.1 R195.1 R196.1 R197.1 R198.1 U15.1(DEVSLP) U15.3(PGTH) U15.16(GND) U15.21(PAD) U16.4(GND) U17.1(DEVSLP) U17.3(PGTH) U17.16(GND) U17.21(PAD) U18.4(GND)
V_RADAR0: C238.1 C239.1 C242.1(+) C243.1 L42.2 R174.2 R175.2 R177.2 TP28.1 U15.4(OUT) U15.5(OUT) U15.6(OUT) U15.7(OUT) U15.8(OUT) U16.1(VCC)
V_RADAR0_unprot: C240.2 R168.1 R176.2 U15.9(IN) U15.10(IN) U15.11(IN) U15.12(IN) U15.13(IN)
V_RADAR1: C253.1 C254.1 C257.1(+) C258.1 L49.2 R188.2 R189.2 R191.2 TP31.1 U17.4(OUT) U17.5(OUT) U17.6(OUT) U17.7(OUT) U17.8(OUT) U18.1(VCC)
V_RADAR1_unprot: C255.2 R169.1 R190.2 U17.9(IN) U17.10(IN) U17.11(IN) U17.12(IN) U17.13(IN)
V_RADAR2_unprot: R170.1
V_RADAR3_unprot: R171.1
radar_0_coax_n: C249.2 ; off-sheet radar_0_coax_n
radar_0_coax_p: C245.1 ; off-sheet radar_0_coax_p
radar_0_coax_se: C245.2 J28.1 L58.1
radar_0_HSD_n: C241.2 ; off-sheet radar_0_HSD_n
radar_0_HSD_p: C244.2 ; off-sheet radar_0_HSD_p
radar_1_coax_n: C264.2 ; off-sheet radar_1_coax_n
radar_1_coax_p: C260.1 ; off-sheet radar_1_coax_p
radar_1_coax_se: C260.2 J30.1 L69.1
radar_1_HSD_n: C256.2 ; off-sheet radar_1_HSD_n
radar_1_HSD_p: C259.2 ; off-sheet radar_1_HSD_p
NetC236_1: C236.1 C237.1 L42.1 L83.2 R185.2
NetC241_1: C241.1 L47.3 U16.3(IO1)
NetC244_1: C244.1 L47.2 U16.5(IO2)
NetC246_1: C246.1 U15.18(DVDT)
NetC247_1: C247.1 J29.3 L45.1
NetC247_2: C247.2 R182.2
NetC248_1: C248.1 J29.1 L46.1
NetC248_2: C248.2 R183.2
NetC249_1: C249.1 R184.2
NetC251_1: C251.1 C252.1 L49.1 L84.2 R199.2
NetC256_1: C256.1 L54.3 U18.3(IO1)
NetC259_1: C259.1 L54.2 U18.5(IO2)
NetC261_1: C261.1 U17.18(DVDT)
NetC262_1: C262.1 J31.3 L52.1
NetC262_2: C262.2 R195.2
NetC263_1: C263.1 J31.1 L53.1
NetC263_2: C263.2 R196.2
NetC264_1: C264.1 R198.2
NetJ27_2: J27.2 R168.2 R169.2 R170.2 R171.2
NetJ29_2: J29.2 L47.1
NetJ29_4: J29.4 L47.4
NetJ31_2: J31.2 L54.1
NetJ31_4: J31.4 L54.4
NetL45_2: L45.2 R174.1
NetL46_2: L46.2 R175.1
NetL51_1: L51.1 L55.2 R125.1
NetL51_2: L51.2 L83.1 R125.2 R185.1
NetL52_2: L52.2 R188.1
NetL53_2: L53.2 R189.1
NetL55_1: L55.1 L57.2
NetL57_1: L57.1 L58.2
NetL62_1: L62.1 L64.2 R126.1
NetL62_2: L62.2 L84.1 R126.2 R199.1
NetL64_1: L64.1 L65.2
NetL65_1: L65.1 L69.2
NetR176_1: R176.1 R178.2 U15.14(EN/UVLO)
NetR177_1: R177.1 TP29.1 U15.20(~{FLT})
NetR178_1: R178.1 R179.2 U15.15(OVP)
NetR180_2: R180.2 U15.17(ILIM)
NetR181_2: R181.2 TP30.1 U15.19(IMON)
NetR190_1: R190.1 R192.2 U17.14(EN/UVLO)
NetR191_1: R191.1 TP32.1 U17.20(~{FLT})
NetR192_1: R192.1 R193.2 U17.15(OVP)
NetR194_2: R194.2 U17.17(ILIM)
NetR197_2: R197.2 TP33.1 U17.19(IMON)

Not connected (* = marked no-connect by the designer): U15 2(PGOOD); U16 2(NC)*; U17 2(PGOOD); U18 2(NC)*

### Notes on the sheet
- Power Selection
- Ilim = 89/Rlim(kohm)
- 88.7k for
  Amp
- 139k for .64Amp
- 1500pf for inrush

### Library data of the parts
C236 C238 C241 C244 C245 C251 C253 C256 C259 C260 = GCM155R71H104KE02D: as C65 on sheet ADAS_SF_Data_Deserializer_Radar
C237 C239 C252 C254 = TMK212BBJ106KG-T: CAP, CERM, 10 µF, 25 V, +/- 10%, X5R, 0805; Manufacturer: Taiyo Yuden; Polarized: N; CompType: Capacitor; Value: 10uF; U/M: EA; Cap_F: 0.00001; Tolerance_%: 10; Value1: Unknown; VDC_V: 25; Value2: 25V; TaMin_C: -55; TaMax_C: 85; Cap_Case: 0805; SizeArea_mm2: 2.5; SizeAreaWB_mm2: 6.75; SizeX_mm: 2; SizeY_mm: 1.25; SizeZ_mm: 1.45; AEC Category: Q200
C240 C255 = GRM188R72A104KA35D: CAP, CERM, 0.1uF, 100V, +/-10%, X7R, 0603; Manufacturer: MuRata; Polarized: N; CompType: Capacitor; U/M: EA; Cap_F: 0.0000001; Tolerance_%: 10; Value1: Unknown; VDC_V: 100; TaMin_C: -55; TaMax_C: 125; Cap_Case: 0603
C242 C257 = EEE-FC1C101P: CAP, AL, 100 µF, 16 V, +/- 20%, 0.4 ohm, SMD; Manufacturer: Panasonic; Polarized: Y; CompType: Capacitor; Value: 100uF; U/M: EA; Cap_F: 0.0001; Tolerance_%: 20; Value1: 0.4 ohm; VDC_V: 16; Value2: 16V; ESR_ohm: 0.4; IRMS_A: 0.15; TaMin_C: -40; TaMax_C: 105; Cap_Case: E; AEC Category: Q200
C243 C258 = CL21A106KAFN3NE: as C62 on sheet ADAS_SF_Data_Deserializer_Radar
C246 C261 = GCM155R71H102KA37D: CAP, CERM, 1000 pF, 50 V, +/- 10%, X7R, AEC-Q200 Grade 1, 0402; Manufacturer: MuRata; Polarized: N; CompType: Capacitor; Value: 1000pF; U/M: EA; Cap_F: 0.000000001; Tolerance_%: 10; Value1: Unknown; VDC_V: 50; Value2: 50V; TaMin_C: -55; TaMax_C: 125; SizeArea_mm2: 0.5; SizeAreaWB_mm2: 3; SizeX_mm: 1; SizeZ_mm: 0.6; AEC Category: Q200; AEC Qualified: Y
C247 C248 C262 C263 = GRM188R72A104KA35D: CAP, CERM, 0.1 µF, 100 V, +/- 10%, X7R, 0603; Manufacturer: MuRata; Polarized: N; CompType: Capacitor; Value: 0.1uF; U/M: EA; Cap_F: 0.0000001; Tolerance_%: 10; Value1: Unknown; VDC_V: 100; Value2: 100V; TaMin_C: -55; TaMax_C: 125; SizeArea_mm2: 1.28; SizeAreaWB_mm2: 4.68; SizeX_mm: 1.6; SizeY_mm: 0.8; SizeZ_mm: 1; AEC Category: Q200
C249 C264 = CGA2B3X7R1H473K050BB: CAP, CERM, 0.047 µF, 50 V, +/- 10%, X7R, AEC-Q200 Grade 1, 0402; Manufacturer: TDK; Polarized: N; CompType: Capacitor; Value: 0.047uF; U/M: EA; Cap_F: 0.000000047; Tolerance_%: 10; ESR_ohm: 0.06407; Value1: 0.06407 ohm; VDC_V: 50; Value2: 50V; IRMS_A: 0.646122; TaMin_C: -55; TaMax_C: 125; SizeArea_mm2: 0.5; SizeAreaWB_mm2: 3; SizeX_mm: 1; SizeZ_mm: 0.6; AEC Category: Q200; AEC Qualified: Y
J27 = TSW-103-07-G-S: Header, 100mil, 3x1, Gold, TH; Manufacturer: Samtec; SymbolCreator: a0799628; Pitch_mm: 2.54; Gender: Male; Shrouded: N; Row_Count: 1; Current_A: 6.3; Voltage_V: 550; Cert_CSA: Y
J28 J30 = 59S20X-400L5-Y: RIGHT ANGLE PLUG FOR PCB; Manufacturer: Rosenberger; SymbolCreator: x0208325; U/M: EA
J29 J31 = D4S20L-40MA5-Z: Right Angle Plug for PCB, TH; Manufacturer: Rosenberger; SymbolCreator: Altium/a0412235
L42 L49 = MPZ1608S102ATA00: Ferrite Bead, 1000 ohm @ 100 MHz, 0.8 A, 0603; Manufacturer: TDK; Imax_A: 0.8; DCR_ohm: 0.3; Value1: 0.3 ohm; Value2: 0.8A; ZTyp@100MHz_Ohm: 1000
L45 L46 L52 L53 = EPL3012-103MLB: Inductor, Shielded, Ferrite, 10 µH, 0.79 A, 0.32 ohm, SMD; Manufacturer: Coilcraft; Value: 10uH; Ind_H: 10.0E-6; Imax_A: 0.79; Irms: 0.79A @ 40C rise; Isat: 0.8A @ 30% inductance drop; DCR_ohm: 0.32; Value2: 0.79A; AEC Category: Q200
L47 L54 = DLW21HN900SQ2L: Coupled inductor, 0.33 A, 0.35 ohm, SMD; Manufacturer: MuRata; SymbolCreator: a0412235; DCR_ohm: 0.35
L51 L62 = LQH3NPZ100MJRL: Inductor, Wirewound, Ferrite, 10 µH, 0.81 A, 0.288 ohm, AEC-Q200 Grade 1, SMD; Manufacturer: MuRata; Value: 10uH; Ind_H: 10.0E-6; Imax_A: 0.81; Irms: 1.2A @ 40C rise; Isat: 0.81A @ 30% inductance drop; DCR_ohm: 0.288; Value2: 0.81A; SizeAreaWB_mm2: 16; SizeArea_mm2: 9; SizeX_mm: 3; SizeZ_mm: 1.2; AEC Category: Q200; AEC Qualified: Y; AEC Grade: 1
L55 L57 L58 L64 L65 L69 = BLM18HE152SN1D: Ferrite Bead, 1500 ohm @ 100 MHz, 0.5 A, 0603; Manufacturer: MuRata; Imax_A: 0.5; Value1: 0.5 ohm; Value2: 0.5A; SizeAreaWB_mm2: 4.68; SizeArea_mm2: 1.28; SizeX_mm: 1.6; SizeY_mm: 0.8; SizeZ_mm: 1; ZTyp@100MHz_Ohm: 1500
L83 L84 = MSS7341-104MLB: Inductor, Shielded Drum Core, Ferrite, 100 µH, 0.71 A, 0.36 ohm, SMD; Manufacturer: Coilcraft; Value: 100uH; Ind_H: 100.0E-6; Imax_A: 0.71; Irms: 1.15A @ 40C rise; Isat: 0.71A @ 30% inductance drop; DCR_ohm: 0.36; Value2: 0.71A; SizeAreaWB_mm2: 86.49; SizeArea_mm2: 53.29; SizeX_mm: 7.3; SizeZ_mm: 4.1; AEC Category: Q200; AEC Qualified: N
R125 R126 = CRCW06034K02FKEA: RES, 4.02 k, 1%, 0.1 W, 0603; Manufacturer: Vishay-Dale; CompType: Resistor; Value: 4.02k; Res_ohm: 4020; Value_Code: 4k02; Tolerance_%: 1; Power_W: 0.1; Value2: 0.1W; VDC_V: 75; TempCo: 100 ppm/C; SizeArea_mm2: 1.28; SizeX_mm: 1.6; SizeY_mm: 0.8; EIA_Code: E96; U/M: EA; AEC Category: Q200
R168-R171 = CRCW06030000Z0EA: RES, 0 ohm, 5%, 0.1W, 0603; Manufacturer: Vishay-Dale; CompType: Resistor; Value_Code: 0000; Tolerance_%: 5; Power_W: 0.1; VDC_V: 75; TempCo: 200 ppm/C; EIA_Code: E24; U/M: EA
R174 R175 R188 R189 = CRCW06030000Z0EA: as R32 on sheet ADAS_SF_Data_Deserializer_Radar
R176 R190 = CRCW0402309KFKED: RES, 309 k, 1%, 0.063 W, 0402; Manufacturer: Vishay-Dale; CompType: Resistor; Value: 309k; Res_ohm: 309000; Tolerance_%: 1; Power_W: 0.063; Value2: 0.063W; VDC_V: 50; TempCo: 100 ppm/C; SizeArea_mm2: 0.5; SizeZ_mm: 0.6; EIA_Code: E96; U/M: EA; AEC Category: Q200
R177 R191 = CRCW0402100KDHEDP: RES, 100 k, 0.5%, 0.063 W, 0402; Manufacturer: Vishay-Dale; CompType: Resistor; Value: 100k; Res_ohm: 100000; Tolerance_%: 0.5; Power_W: 0.063; Value2: 0.063W; VDC_V: 50; TempCo: 50 ppm/C; SizeX_mm: 1; SizeZ_mm: 0.6; EIA_Code: E192; U/M: EA; AEC Category: Q200
R178 R192 = CRCW040269K8FKED: RES, 69.8 k, 1%, 0.063 W, 0402; Manufacturer: Vishay-Dale; CompType: Resistor; Value: 69.8k; Res_ohm: 69800; Value_Code: 69k8; Tolerance_%: 1; Power_W: 0.063; Value2: 0.063W; VDC_V: 50; TempCo: 100 ppm/C; SizeArea_mm2: 0.5; SizeZ_mm: 0.6; EIA_Code: E96; U/M: EA; AEC Category: Q200
R179 R193 = CRCW040230K9FKED: RES, 30.9 k, 1%, 0.063 W, 0402; Manufacturer: Vishay-Dale; CompType: Resistor; Value: 30.9k; Res_ohm: 30900; Value_Code: 30k9; Tolerance_%: 1; Power_W: 0.063; Value2: 0.063W; VDC_V: 50; TempCo: 100 ppm/C; SizeArea_mm2: 0.5; SizeZ_mm: 0.6; EIA_Code: E96; U/M: EA; AEC Category: Q200
R180 R194 = CRCW040244K2FKED: RES, 44.2 k, 1%, 0.063 W, 0402; Manufacturer: Vishay-Dale; CompType: Resistor; Value: 44.2k; Res_ohm: 44200; Value_Code: 44k2; Tolerance_%: 1; Power_W: 0.063; Value2: 0.063W; VDC_V: 50; TempCo: 100 ppm/C; SizeArea_mm2: 0.5; SizeZ_mm: 0.6; EIA_Code: E96; U/M: EA; AEC Category: Q200
R181 R197 = CRCW040216K9FKED: RES, 16.9 k, 1%, 0.063 W, 0402; Manufacturer: Vishay-Dale; CompType: Resistor; Value: 16.9k; Res_ohm: 16900; Value_Code: 16k9; Tolerance_%: 1; Power_W: 0.063; Value2: 0.063W; VDC_V: 50; TempCo: 100 ppm/C; SizeArea_mm2: 0.5; SizeZ_mm: 0.6; EIA_Code: E96; U/M: EA; AEC Category: Q200
R182 R183 R195 R196 = CRCW040249R9FKED: RES, 49.9, 1%, 0.063 W, 0402; Manufacturer: Vishay-Dale; CompType: Resistor; Value: 49.9; Value_Code: 49R9; Tolerance_%: 1; Power_W: 0.063; Value2: 0.063W; VDC_V: 50; TempCo: 100 ppm/C; SizeArea_mm2: 0.5; SizeZ_mm: 0.6; EIA_Code: E96; U/M: EA; AEC Category: Q200
R184 R198 = CRCW040249R9FKED: RES, 49.9, 1%, 0.063 W, 0402; Manufacturer: Vishay-Dale; CompType: Resistor; Value: 49.9; Value_Code: 49R9; Tolerance_%: 1; Power_W: 0.063; Value2: 0.063W; VDC_V: 50; TempCo: 100 ppm/C; EIA_Code: E96; U/M: EA; SizeArea_mm2: 0.5; SizeZ_mm: 0.6; AEC Category: Q200
R185 R199 = CRCW06032K00FKEA: RES, 2.00 k, 1%, 0.1 W, 0603; Manufacturer: Vishay-Dale; CompType: Resistor; Value: 2.00k; Res_ohm: 2000; Value_Code: 2k00; Tolerance_%: 1; Power_W: 0.1; Value2: 0.1W; VDC_V: 75; TempCo: 100 ppm/C; SizeArea_mm2: 1.28; SizeX_mm: 1.6; SizeY_mm: 0.8; EIA_Code: E96; U/M: EA; AEC Category: Q200
TP28 TP31 = 5000: Test Point, Miniature, Red, TH; Manufacturer: Keystone; CompType: Test Point Loop; U/M: EA
TP29 TP30 TP32 TP33 = 5004: Test Point, Miniature, Yellow, TH; Manufacturer: Keystone; CompType: Test Point Loop; U/M: EA
U15 U17 = TPS25940ARVCR: 2.7 – 18V eFuse with True Reverse Blocking and DevSleep Support for SSDs, RVC0020A; Alternate PartNumber: TPS25940ARVCT; Manufacturer: Texas Instruments; SymbolCreator: a0411947; SizeArea_mm2: 12; SizeAreaWB_mm2: 20; SizeX_mm: 3; SizeY_mm: 4; SizeZ_mm: 0.8; CompType: IC; U/M: EA
U16 U18 = TPD2E001DRLR: Low-Capacitance + / - 15 kV ESD-Protection Array for High-Speed Data Interfaces, 2 Channels, -40 to +85 degC, 5-pin SOT (DRL), Green (RoHS & no Sb/Br); Manufacturer: Texas Instruments; Alternate PartNumber: Equivalent; Breakdown Voltage(Min)(V): 11; IEC 61000-4-2 Air-Gap(+/- kV): 15; IEC 61000-4-2 Contact(+/- kV): 8; IO Capacitance(Typ)(pF): 1.5; IO Leakage Current(nA): 1; SubFamily: ESD Solution; USB High Speed: TRUE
